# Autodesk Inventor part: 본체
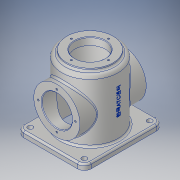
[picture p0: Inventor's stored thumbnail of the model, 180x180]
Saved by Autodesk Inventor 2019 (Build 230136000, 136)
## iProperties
Created: 2020-12
Part Number: 본체
Material: 알루미늄 6061
Document SubType Name: Modeling
Designer: jun-1-11
Density: 2.7 g/cm^3
Appearance: 알루미늄 - 평지
Mass: 1235.46 g
Surface Area: 1067.12 cm^2
Volume: 457.576 cm^3
Author: jun-1-11
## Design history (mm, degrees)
sketch "스케치1"
  geometry: L1 (60, 70)-(-60, 70); L2 (-60, 70)-(-60, -70); L3 (-60, -70)-(60, -70); L4 (60, -70)-(60, 70); L5 (60, 70)-(-60, -70); L6 (-60, 70)-(60, -70); 1 further point
  constraints: 12 end point, 2 midpoint, 2 parallel, 1 horizontal, 1 perpendicular
  dimensions: "d0" = 120 distance of L3.end L2.end; "d1" = 140 distance of L2.end L1.end
extrude "돌출1" new body sketch "스케치1" distance "d2" = 10; taper "d3" = 0 deg
fillet "모깎기1" dims "d4" = 12
sketch "스케치2" dims "d19" = 5
  geometry: A1 r 12 centre (-48, 58) between (-48, 70) and (-60, 58) reference; 2 further points
  constraints: 1 coincident
hole "구멍1" sketch "스케치2" at (-48, 58) diameter "d5" = 9; stored, may be unused: countersink angle "d9" = 90 deg, drill point angle "d11" = 0 deg; dims "d6" = 18, "d7" = 4, "d8" = 2, "d10" = 22, "d19" = 5
sketch "스케치3"
  geometry: C1 r 50 at (0, 0); 1 further point
  constraints: 1 centre point, 1 coincident
  dimensions: "d12" = 100 diameter of C1
extrude "돌출2" join sketch "스케치3" distance "d13" = 110; taper "d14" = 0 deg
sketch "스케치5"
  geometry: C1 r 41 at (0, 0); 1 further point
  constraints: 1 centre point, 1 coincident
  dimensions: "d18" = 82 diameter of C1
extrude "돌출4" join sketch "스케치5" distance "d19" = 5; taper "d20" = 0 deg
sketch "스케치6"
  geometry: C1 r 27 at (0, 0); 1 further point
  constraints: 1 centre point, 1 coincident
  dimensions: "d21" = 54 diameter of C1
extrude "돌출5" cut sketch "스케치6" distance "d22" = 13; taper "d23" = 0 deg
sketch "스케치7"
  geometry: L1 (42, 0)-(-42, 0) reference; C1 r 41 at (0, 60); 1 further point
  constraints: 1 centre point, 1 vertical alignment
  dimensions: "d24" = 82 diameter of C1; "d25" = 60 distance from line of L1 C1.centre
extrude "돌출6" join sketch "스케치7" stored distance "d26" = 118; taper "d27" = 0 deg
sketch "스케치8"
  geometry: C1 r 27 at (0, 60); 2 further points
  constraints: 1 centre point, 1 vertical alignment, 1 other
  dimensions: "d28" = 54 diameter of C1; "d29" = 60 distance of point (0, 0) C1.centre
extrude "돌출7" cut sketch "스케치8" stored distance "d30" = 118; taper "d31" = 0 deg
sketch "스케치9"
  geometry: C1 r 42 at (0, 0); 1 further point
  constraints: 1 centre point, 1 coincident
  dimensions: "d32" = 84 diameter of C1
extrude "돌출8" cut sketch "스케치9" distance "d33" = 112; taper "d34" = 0 deg
sketch "스케치10"
  geometry: C1 r 41 at (0, 0) reference; 2 further points
  constraints: 1 vertical alignment
  dimensions: "d35" = 33 distance of C1.centre point (0, 33)
hole "구멍2" sketch "스케치10" at (0, 33) diameter "d36" = 3.242; stored, may be unused: countersink angle "d40" = 90 deg, drill point angle "d42" = 118 deg; dims "d37" = 8, "d38" = 4, "d39" = 2, "d41" = 10
sketch "스케치11"
  geometry: C1 r 41 at (0, 0) reference; 2 further points
  constraints: 1 vertical alignment
  dimensions: "d46" = 33 distance of point (0, 0) point (0, 33)
hole "구멍3" sketch "스케치11" at (0, 33) diameter "d47" = 3.242; stored, may be unused: countersink angle "d51" = 90 deg, drill point angle "d53" = 118 deg; dims "d48" = 8, "d49" = 4, "d50" = 2, "d52" = 10
node "작업 평면1"
sketch "스케치12"
  geometry: L1 (-10, 58)-(-10, -58) reference; 2 further points
  constraints: 1 other
feature "엠보싱1" sketch "스케치12" dims "d0" = 120, "d1" = 140, "d58" = 0.5, "d59" = 0
fillet "모깎기2" dims "d60" = 3
fillet "모깎기3" dims "d61" = 6
chamfer "모따기1" distance "d62" = 1; stored, may be unused: second distance "d63" = 2, angle "d64" = 45 deg
fillet "모깎기4" dims "d65" = 3
node "솔리드1"
mirror "미러1"
mirror "미러2"
pattern_circular "원형 패턴1" dims angle "d44" = 360 deg
mirror "미러3"
pattern_circular "원형 패턴2" dims angle "d55" = 360 deg
